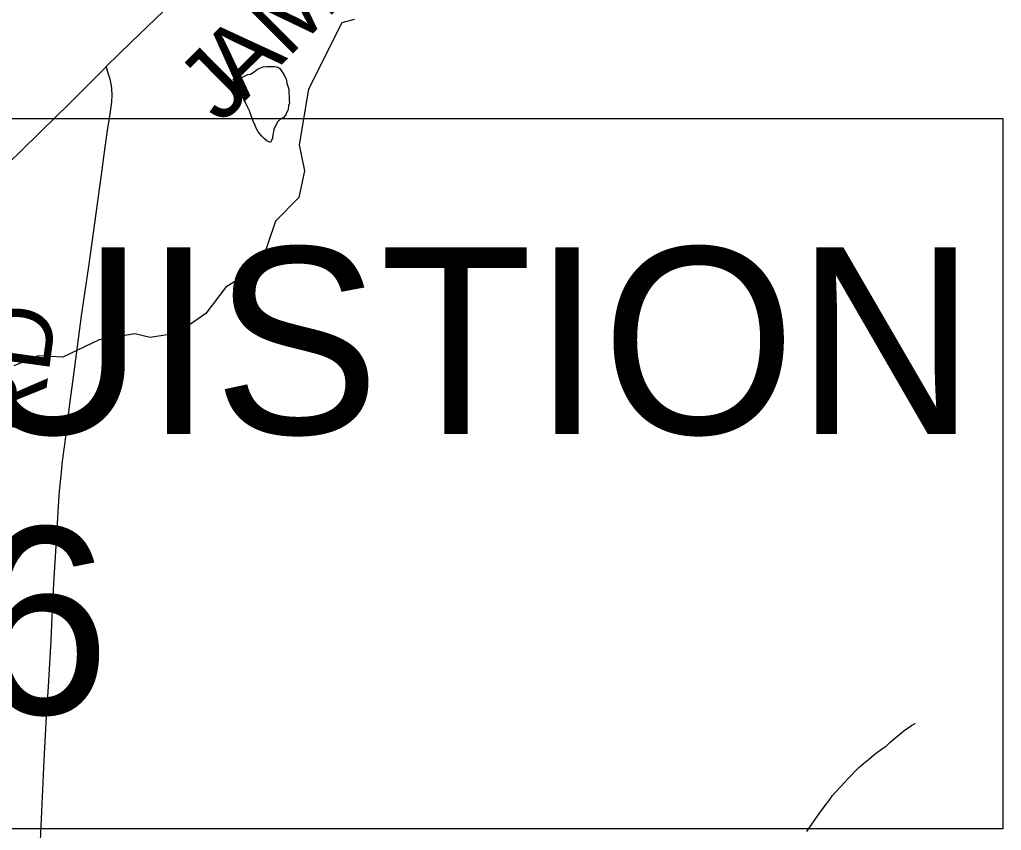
# Model space of a CAD drawing. Extents: x -13.9 to 69.1, y -25.2 to 26.1.
# Drawn here: x 3.245 to 3.981, y 16.445 to 17.053 of the extents above; entities that cross this region are included whole.
import ezdxf

# ---------------------------------------------------------------- set-up
doc = ezdxf.new("R2010")
doc.units = 0
for name, color, linetype in [('GM_X_County_Road', 7, 'Continuous'), ('GM_X_County_Road_Text', 7, 'Continuous'), ('GM_X_Minor_Lake', 7, 'Continuous'), ('GM_X_Minor_River', 7, 'Continuous'), ('GM_X_Township_Road', 7, 'Continuous'), ('GM_X_Township_Road_Text', 7, 'Continuous'), ('SH_Text', 7, 'Continuous')]:
    doc.layers.add(name, color=color, linetype=linetype)

msp = doc.modelspace()

# ---------------------------------------------------------------- linework, layer by layer
at = {"layer": 'GM_X_County_Road'}
for points in [[(3.31011, 17.01776), (3.32883, 17.03596), (3.37112, 17.07699)], [(3.23162, 16.94057), (3.24533, 16.95355), (3.26127, 16.96918), (3.28248, 16.99005), (3.30997, 17.01763), (3.31011, 17.01776)]]:
    msp.add_lwpolyline(points, dxfattribs=at)
at = {"layer": 'GM_X_Minor_Lake'}
msp.add_lwpolyline([(3.40513, 17.00824), (3.40952, 17.00855), (3.41325, 17.01033), (3.41631, 17.01175), (3.41833, 17.01209), (3.42105, 17.01388), (3.42343, 17.01567), (3.42581, 17.01673), (3.42784, 17.01744), (3.43021, 17.01778), (3.43189, 17.01776), (3.43358, 17.01774), (3.43628, 17.01771), (3.43864, 17.01732), (3.44032, 17.01621), (3.44231, 17.01328), (3.44364, 17.01072), (3.44497, 17.00852), (3.44561, 17.00524), (3.44627, 17.00306), (3.44692, 17.00087), (3.44689, 16.99796), (3.44721, 16.99541), (3.44718, 16.9925), (3.44749, 16.99032), (3.4468, 16.98851), (3.44643, 16.98524), (3.4454, 16.98343), (3.44471, 16.98163), (3.443, 16.97946), (3.44096, 16.9784), (3.43858, 16.97624), (3.43582, 16.97046), (3.43547, 16.96864), (3.43511, 16.96683), (3.43474, 16.96392), (3.43336, 16.96067), (3.43067, 16.96179), (3.42866, 16.96363), (3.42666, 16.96547), (3.42399, 16.96877), (3.42266, 16.97096), (3.42167, 16.97352), (3.42035, 16.97681), (3.4187, 16.98082), (3.41739, 16.98447), (3.41607, 16.9874), (3.41441, 16.99069), (3.41342, 16.99251), (3.40513, 17.00824)], dxfattribs=at)
at = {"layer": 'GM_X_Minor_River'}
for points in [[(3.4959, 17.05293), (3.48662, 17.05052), (3.46163, 17.0008), (3.45462, 16.95913), (3.45873, 16.93945), (3.4544, 16.91954), (3.43694, 16.90166), (3.42567, 16.86842), (3.3998, 16.85213), (3.38468, 16.8324), (3.36355, 16.81785), (3.34293, 16.81455), (3.3315, 16.81728), (3.30478, 16.81263), (3.27761, 16.79963), (3.25907, 16.80066), (3.24075, 16.79333)], [(3.83558, 16.44393), (3.83832, 16.44789), (3.84106, 16.45186), (3.8438, 16.45583), (3.84654, 16.45979), (3.84928, 16.4634), (3.85201, 16.467), (3.85475, 16.47097), (3.85782, 16.4742), (3.86055, 16.47708), (3.86396, 16.48104), (3.86635, 16.48356), (3.86907, 16.48607), (3.87147, 16.48895), (3.87453, 16.49182), (3.87794, 16.49505), (3.88168, 16.49792), (3.88543, 16.50114), (3.88883, 16.50365), (3.89223, 16.50615), (3.89529, 16.5083), (3.89767, 16.51081), (3.90107, 16.51332), (3.90958, 16.52049), (3.9123, 16.52227), (3.91434, 16.5237), (3.91603, 16.52441), (3.91672, 16.52513), (3.91603, 16.52441)]]:
    msp.add_lwpolyline(points, dxfattribs=at)
at = {"layer": 'GM_X_Township_Road'}
msp.add_lwpolyline([(3.26067, 16.43688), (3.26361, 16.49748), (3.26533, 16.53014), (3.26662, 16.5527), (3.26863, 16.58713), (3.26949, 16.60495), (3.27083, 16.62989), (3.27292, 16.66611), (3.27416, 16.68807), (3.27473, 16.69576), (3.27501, 16.6993), (3.2764, 16.71347), (3.2773, 16.72174), (3.27888, 16.73411), (3.28144, 16.75415), (3.28284, 16.76475), (3.28521, 16.78301), (3.28848, 16.80773), (3.29145, 16.83069), (3.29698, 16.86769), (3.3005, 16.89294), (3.30345, 16.91471), (3.3051, 16.92586), (3.30659, 16.93644), (3.30886, 16.95349), (3.31086, 16.96819), (3.31265, 16.98051), (3.31414, 16.99109), (3.31448, 16.99643), (3.31424, 17.00117), (3.31379, 17.0047), (3.31298, 17.00817), (3.31207, 17.0112), (3.31011, 17.01776)], dxfattribs=at)
at = {"layer": 'SH_Text'}
msp.add_lwpolyline([(2.09646, 16.97889), (3.98257, 16.97889), (3.98257, 16.44591), (2.09646, 16.44591)], close=True, dxfattribs=at)

# ---------------------------------------------------------------- texts
at = {"layer": 'GM_X_County_Road_Text'}
for s, rotation, p in [('M', 44.91297, (3.44598, 17.02345)), ('A', 44.91427, (3.41336, 16.99093)), ('J', 44.91524, (3.39596, 16.97358))]:
    msp.add_text(s, height=0.05263, rotation=rotation, dxfattribs=at).set_placement(p)
at = {"layer": 'GM_X_Township_Road_Text'}
msp.add_text('RD', height=0.050631, rotation=82.17368, dxfattribs=at).set_placement((3.26009, 16.73868))
at = {"layer": 'SH_Text'}
for s, p in [('BEGIN ACQUISTION', (2.16291, 16.74212)), ('STA. 9+02.56', (2.16291, 16.53212))]:
    msp.add_text(s, height=0.14, dxfattribs=at).set_placement(p)

doc.saveas('drawing.dxf')
